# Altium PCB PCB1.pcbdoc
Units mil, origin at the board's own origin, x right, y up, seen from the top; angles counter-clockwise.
Board outline 2875 x 2510 mil, 2 copper layers (Top Layer, Bottom Layer); 42 components, 21 nets, 120 pads, 43 vias.
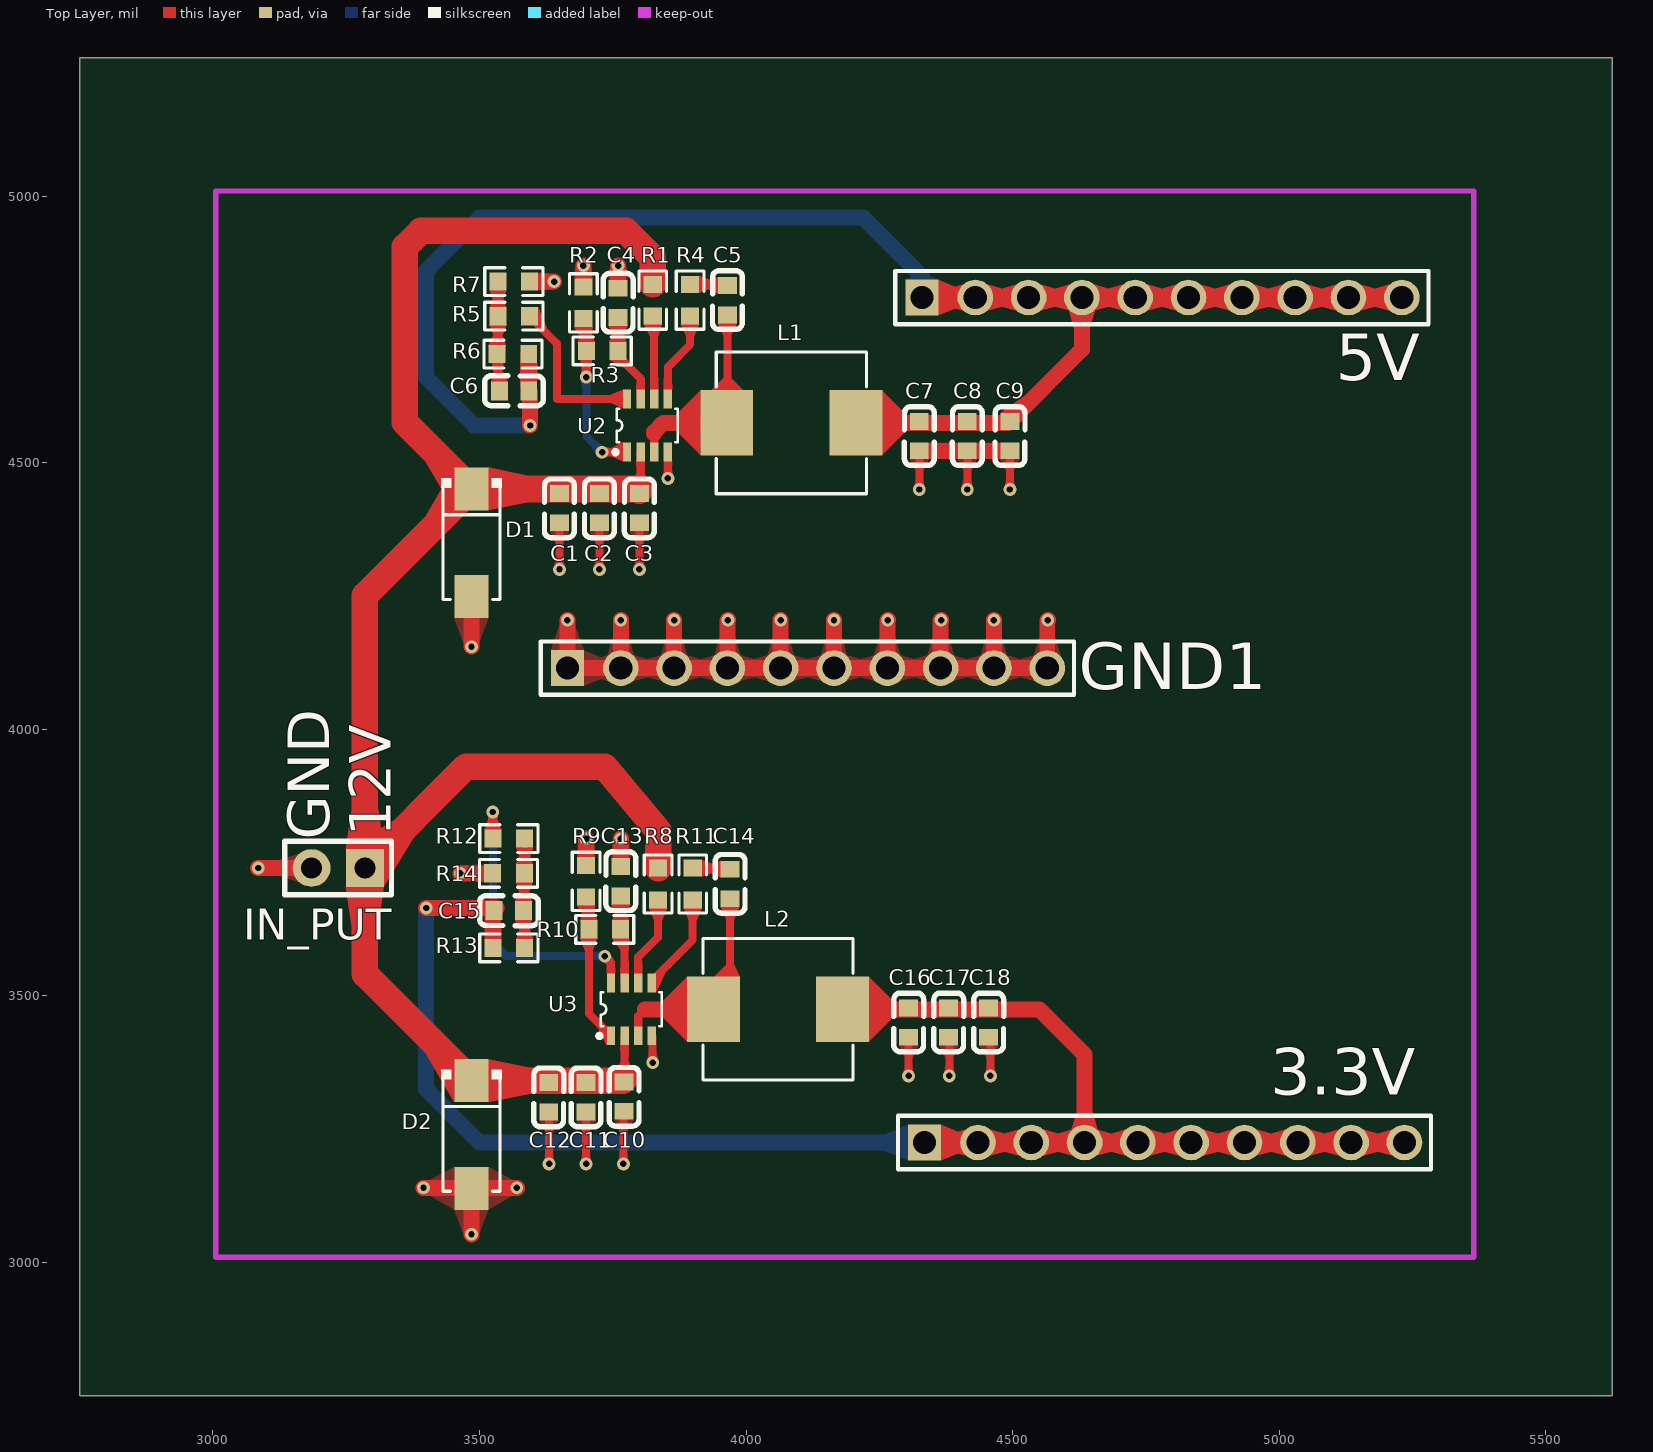
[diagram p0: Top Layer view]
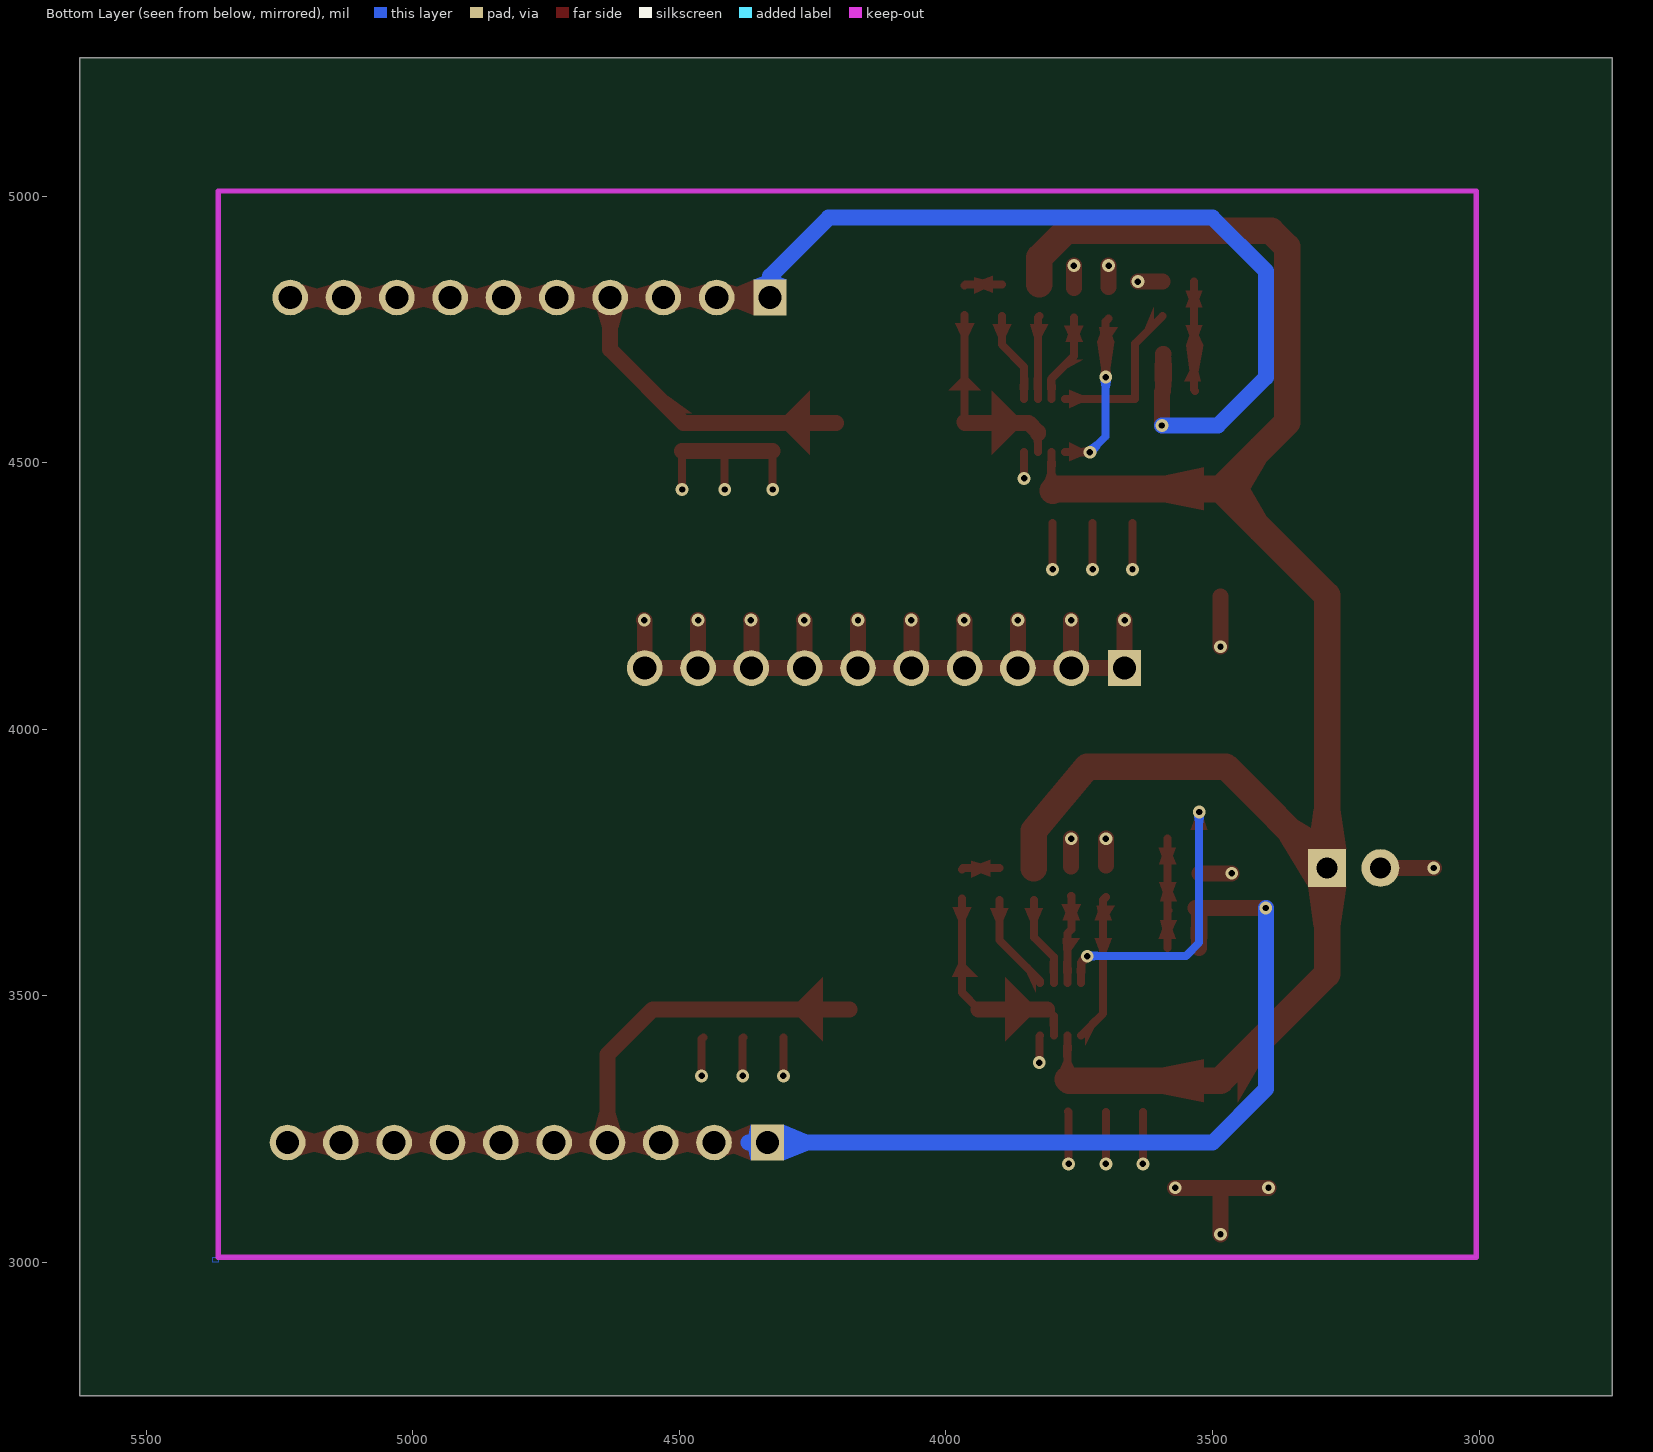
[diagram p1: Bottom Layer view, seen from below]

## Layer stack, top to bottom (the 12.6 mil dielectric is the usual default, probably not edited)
Top Layer: signal copper (thickness not stored)
Dielectric: dielectric 12.6, FR-4, Dk 4.8
Bottom Layer: signal copper (thickness not stored)

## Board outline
5625,2750 2750,2750 2750,5260 5625,5260

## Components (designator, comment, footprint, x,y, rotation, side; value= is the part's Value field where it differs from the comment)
3.3V "HDR-M_2.54_1x10P" HDR-TH_10P-P2.54-V-M-1 4785,3225 r0 top
5V "HDR-M_2.54_1x10P" HDR-TH_10P-P2.54-V-M-1 4780,4810 r0 top
C1 "CAP_0603" C0603 3650,4415 r90 top
C2 "CAP_0603" C0603 3725,4415 r90 top
C3 "CAP_0603" C0603 3800,4415 r90 top
C4 "CAP_0603" C0603 3760,4800 r270 top
C5 "CAP_0603" C0603 3965,4805 r270 top
C6 "CAP_0603" C0603 3565,4635 r0 top
C7 "CAP_0603" C0603 4325,4550 r270 top
C8 "CAP_0603" C0603 4415,4550 r270 top
C9 "CAP_0603" C0603 4495,4550 r270 top
C10 "CAP_0603" C0603 3771.35,3311.07 r90 top
C11 "CAP_0603" C0603 3700,3310 r90 top
C12 "CAP_0603" C0603 3630,3310 r90 top
C13 "CAP_0603" C0603 3765,3715 r270 top
C14 "CAP_0603" C0603 3970,3710 r270 top
C15 "CAP_0603" C0603 3555,3660 r180 top
C16 "CAP_0603" C0603 4305,3450 r270 top
C17 "CAP_0603" C0603 4380,3450 r270 top
C18 "CAP_0603" C0603 4455,3450 r270 top
D1 "SMAJ12A_C220440" SMA_L4.4-W2.8-LS5.4-RD 3485,4350 r270 top
D2 "SMAJ12A_C220440" SMA_L4.4-W2.8-LS5.4-RD 3485,3240 r270 top
GND1 "HDR-M_2.54_1x10P" HDR-TH_10P-P2.54-V-M-1 4115,4115 r0 top
IN_PUT "HDR-M_2.54_1x2P" HDR-TH_2P-P2.54-V-M-1 3235,3740 r180 top
L1 "MHCI06030-4R7M-R8" IND-SMD_L7.3-W6.6_MHCI06030 4085,4575 r0 top
L2 "MHCI06030-4R7M-R8" IND-SMD_L7.3-W6.6_MHCI06030 4060,3475 r0 top
R1 "Res_0603" R0603 3825,4805 r270 top
R2 "Res_0603" R0603 3695,4800 r270 top
R3 "Res_0603" R0603 3730,4710 r0 top
R4 "Res_0603" R0603 3895,4805 r90 top
R5 "Res_0603" R0603 3564.39,4775 r180 top
R6 "Res_0603" R0603 3562.72,4703.95 r0 top
R7 "Res_0603" R0603 3564.39,4840 r180 top
R8 "Res_0603" R0603 3835,3710 r270 top
R9 "Res_0603" R0603 3700,3715 r270 top
R10 "Res_0603" R0603 3735,3625 r0 top
R11 "Res_0603" R0603 3900,3710 r90 top
R12 "Res_0603" R0603 3555,3795 r0 top
R13 "Res_0603" R0603 3555,3590 r180 top
R14 "Res_0603" R0603 3554.39,3729.99 r0 top
U2 "MP2315SGJ-Z" TSOT-23-8_L2.9-W1.6-P0.65-LS2.8-BL 3815,4570 r0 top
U3 "MP2315SGJ-Z" TSOT-23-8_L2.9-W1.6-P0.65-LS2.8-BL 3785,3475 r0 top

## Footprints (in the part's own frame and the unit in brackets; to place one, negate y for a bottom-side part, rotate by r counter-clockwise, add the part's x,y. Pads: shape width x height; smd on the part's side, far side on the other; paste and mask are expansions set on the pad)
C0603 [mm]
  rect 0.8x0.9 smd: 1(-0.7,0) 2(0.7,0)
  silkscreen extent -1.41,-0.71 1.39,0.72
HDR-TH_2P-P2.54-V-M-1 [mm]
  rect 1.8x1.8 hole 1: 1(-1.27,0)
  round 1.8 hole 1: 2(1.27,0)
  silkscreen extent -2.54,-1.27 2.54,1.27
HDR-TH_10P-P2.54-V-M-1 [mm]
  rect 1.575x1.7 hole 1.1: 1(-11.43,0)
  round 1.7 hole 1.1: 2(-8.89,0) 3(-6.35,0) 4(-3.81,0) 5(-1.27,0) 6(1.27,0) 7(3.81,0) 8(6.35,0) 9(8.89,0) 10(11.43,0)
  silkscreen extent -12.7,-1.27 12.7,1.27
IND-SMD_L7.3-W6.6_MHCI06030 [mm]
  rect 2.524x3.12 smd: 1(-3.078,0) 2(3.078,0)
  silkscreen extent -3.58,-3.38 3.58,3.38
R0603 [mil]
  rect 31.75x34.02 smd: 1(-29.66,0) 2(29.66,0)
  silkscreen extent -55,-26 55,26
SMA_L4.4-W2.8-LS5.4-RD [mil]
  rect 80.57x63.78 smd: 1(-101,0) 2(101,0)
  silkscreen extent -121,-57 106,57
TSOT-23-8_L2.9-W1.6-P0.65-LS2.8-BL [mm]
  rect 0.4x0.9 smd: 1(-0.975,-1.26) 2(-0.325,-1.26) 3(0.325,-1.26) 4(0.975,-1.26) 5(0.975,1.26) 6(0.325,1.26) 7(-0.325,1.26) 8(-0.975,1.26)
  silkscreen extent -1.62,-1.37 1.45,0.8

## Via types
v1: diameter 24.02, hole 12.01, Top Layer to Bottom Layer, 43 vias

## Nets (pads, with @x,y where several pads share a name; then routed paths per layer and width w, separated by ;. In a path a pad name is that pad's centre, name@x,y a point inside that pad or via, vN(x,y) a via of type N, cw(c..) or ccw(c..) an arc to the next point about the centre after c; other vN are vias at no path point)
$1N440: R1.2 U2.6 | length 156.9
  Top Layer w15: R1.2 3827.8,4772.55 U2.6
$1N712: C4.2 R3.2 U2.7 | length 170.8
  Top Layer w15: R3.2@3759.66,4700 R3.2@3760,4700.34 ; C4.2 R3.2@3760,4700.34 ; U2.7 3802.2,4658.14 R3.2@3760,4700.34
$1N792: R2.2 R3.1 U2.1 | length 311.6
  Top Layer w15: R2.2 3700.34,4765 v1(3700.34,4660.87) ; v1(3730,4520) 3776.22,4520 U2.1
  Bottom Layer w15: v1(3700.34,4660.87) 3700.34,4549.66 v1(3730,4520)
$1N1001: R4.1 U2.5 | length 173
  Top Layer w15: U2.5 3853.39,4680 3895,4721.61 R4.1
$1N1049: C5.1 R4.2 | length 70.9
  Top Layer w15: R4.2 3962.9,4834.66 C5.1
$1N1375: C5.2 L1.1 U2.3 | length 383.5
  Top Layer w15: U2.3 3827.8,4555 ; L1.1@3965,4576.18 C5.2
  Top Layer w30: 3827.8,4555 3827.8,4557.8 3845,4575 L1.1 L1.1@3965,4576.18
$1N1427: R5.1 U2.8 | length 307.9
  Top Layer w15: R5.1 3645,4724.05 3645,4620 3776.22,4620 U2.8
$1N1780: C6.1 R5.2 R6.1 R7.2 | length 205.9
  Top Layer w15: C6.1@3532.44,4635 3534.73,4637.29 R5.2 R7.2
$1N2972: R8.2 U3.6 | length 171.1
  Top Layer w15: U3.6 3797.8,3572.8 3835,3610 R8.2
$1N2996: C13.2 R10.2 U3.7 | length 166.1
  Top Layer w15: C13.2 3764.66,3687.1 R10.2 3772.2,3617.45 U3.7
$1N3001: R9.2 R10.1 U3.1 | length 279.3
  Top Layer w15: R9.2 3705.34,3680 R10.1 3705.34,3466.67 U3.1
$1N3008: R11.1 U3.5 | length 187.5
  Top Layer w15: U3.5 3823.39,3528.39 3900,3605 R11.1
$1N3010: C14.1 R11.2 | length 70.9
  Top Layer w15: R11.2 3967.9,3739.66 C14.1
$1N3012: C14.2 L2.1 U3.3 | length 403.8
  Top Layer w15: U3.3 3797.8,3462.8 3810,3475 ; L2.1 3970,3506.18 C14.2
  Top Layer w30: 3810,3475 L2.1
$1N3019: R12.1 U3.8 | length 570.4
  Top Layer w15: v1(3525,3845) 3525.34,3844.66 R12.1 ; v1(3735,3574.5) 3746.61,3562.88 U3.8
  Bottom Layer w15: v1(3525,3845) 3525,3600 3550,3575 3734.5,3575 v1(3735,3574.5)
$1N3044: C15.1 R12.2 R13.1 R14.2 | length 206.7
  Top Layer w15: R13.1 3584.66,3657.9 C15.1 3584.05,3661.49 R14.2 3584.66,3730.6 R12.2
+3.3V: 3.3V.1 3.3V.2 3.3V.3 3.3V.4 3.3V.5 3.3V.6 3.3V.7 3.3V.8 3.3V.9 3.3V.10 C15.2 C16.1 C17.1 C18.1 L2.2 R13.2 | length 3115
  Top Layer w30: v1(3400,3665) 3531.82,3665 3525.34,3658.52 R13.2 ; L2.2 4550,3475 4635,3390 3.3V.4 ; 3.3V.1 3.3V.2 3.3V.3 3.3V.4 ; 3.3V.10 3.3V.9 3.3V.8 3.3V.7 3.3V.6 3.3V.5 3.3V.4
  Bottom Layer w30: v1(3400,3665) 3400,3325 3500,3225 3.3V.1 4370,3225
+5V: 5V.1 5V.2 5V.3 5V.4 5V.5 5V.6 5V.7 5V.8 5V.9 5V.10 C6.2 C7.1 C8.1 C9.1 L1.2 R6.2 | length 3097.9
  Top Layer w30: R6.2 3592.56,4703.76 C6.2@3592.56,4639.63 ; C6.2 3595,4632.56 v1(3595,4570) ; L1.2 4492.44,4575 4630,4712.56 5V.4 ; 5V.1 5V.2 5V.3 5V.4 ; 5V.10 5V.9 5V.8 5V.7 5V.6 5V.5 5V.4
  Bottom Layer w30: v1(3595,4570) 3490,4570 3400,4660 3400,4860 3500,4960 4220,4960 4330,4850 5V.1
+12V: C1.2 C2.2 C3.2 C10.2 C11.2 C12.2 D1.1 D2.1 IN_PUT.1 R1.1 R8.1 U2.2 U3.2 | length 3843.7
  Top Layer w15: C10.2@3772.2,3344.48 U3.2 ; C3.2@3800,4447.56 3802.2,4449.77 U2.2
  Top Layer w50: C10.2@3771.35,3343.63 3768.72,3341 D2.1 3285,3541 IN_PUT.1 ; C3.2@3800,4447.56 3796.56,4451 D1.1 ; R1.1 3825,4885 3775,4935 3390,4935 3360,4905 3360,4576 D1.1 ; R8.1 3835,3810 3735,3930 3475,3930 IN_PUT.1 ; IN_PUT.1 3285,4251 D1.1
GND: C1.1 C2.1 C3.1 C4.1 C7.2 C8.2 C9.2 C10.1 C11.1 C12.1 C13.1 C16.2 C17.2 C18.2 D1.2 D2.2 GND1.1 GND1.2 GND1.3 GND1.4 GND1.5 GND1.6 GND1.7 GND1.8 GND1.9 GND1.10 IN_PUT.2 R2.1 R7.1 R9.1 R14.1 U2.4 U3.4 | length 3813.5
  Top Layer w15: C12.1 3630.49,3281.95 v1(3630.49,3185) ; v1(3650,4300) C1.1 ; v1(3700.01,3185) C11.1 ; v1(3725,4300) C2.1 ; v1(3770,3185) 3770,3282.16 C10.1 ; v1(3800,4300) C3.1 ; U3.4 3825,3423.78 v1(3825,3375) ; v1(3853.39,4470.71) U2.4 ; v1(4305,3350) C16.2 ; v1(4325,4450) C7.2 ; C17.2 4381.2,3421.24 v1(4381.2,3350) ; v1(4415,4450) C8.2 ; C18.2 4458.35,3419.09 v1(4458.35,3350) ; v1(4495,4450) C9.2
  Top Layer w30: v1(3085,3740) IN_PUT.2 ; v1(3395,3140) 3484,3140 D2.2 ; v1(3464.09,3729.99) R14.1 ; v1(3485,3052.8) D2.2 ; v1(3485,4155) D1.2 ; v1(3570,3140) 3486,3140 D2.2 ; R7.1 v1(3640,4840) ; v1(3665,4205) GND1.1 GND1.2 ; R2.1 v1(3695,4870) ; R9.1 v1(3700,3795) ; C4.1 v1(3760,4870) ; C13.1 v1(3765,3795) ; v1(3765,4205) GND1.2 ; v1(3865,4205) GND1.3 ; v1(3965.97,4205) 3965,4204.03 GND1.4 ; v1(4065,4205) GND1.5 ; v1(4165,4205) GND1.6 ; v1(4265.97,4205) 4265,4204.03 GND1.7 ; C7.2 C8.2 C9.2 ; v1(4365.97,4205) 4365,4204.03 GND1.8 ; v1(4465,4205) GND1.9 ; v1(4565.97,4205) 4565,4204.03 GND1.10 GND1.9 ; GND1.2 GND1.3 ; GND1.3 GND1.4 ; GND1.4 GND1.5 ; GND1.5 GND1.6 ; GND1.6 GND1.7 ; GND1.7 GND1.8 ; GND1.8 GND1.9
  other v1: 3853.39,4470.71 3853.39,4470.71
"": 

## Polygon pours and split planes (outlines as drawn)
GND on Bottom Layer (solid, remove dead copper, pour order 1): 5365,3000 5375,3000 5375,3010 5365,3010
GND on Bottom Layer (solid, pour order 2): 3005,3010 5365,3010 5365,5010 3005,5010
GND on Top Layer (solid, remove dead copper, pour order 0): 3000,3010 5365,3010 5365,5010 3000,5010

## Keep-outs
Board Outline Layer:
  lines w10 net "": 3005,3010 5365,3010 5365,5010 3005,5010 3005,3010

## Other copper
Top Layer:
  region net +12V: 3809.7,4480.81 3794.7,4480.81 3782.28,4458.31 3817.72,4458.31
  region net $1N712: 3752.5,4734.19 3767.5,4734.19 3777.72,4756.69 3742.28,4756.69
  region net $1N792: 3692.84,4731.96 3707.84,4731.96 3712.01,4754.46 3677.99,4754.46
  region net $1N712: 3772.65,4677.08 3791.45,4679.5 3775.54,4692.99 3743.78,4692.99
  region net $1N712: 3752.5,4749.51 3743.78,4727.01 3775.54,4727.01 3767.5,4749.51
  region net $1N792: 3692.84,4670.49 3707.84,4670.49 3716.22,4727.01 3684.46,4727.01
  region net $1N792: 3692.84,4749.51 3684.46,4727.01 3716.22,4727.01 3707.84,4749.51
  region net +12V: 3400.08,4401.43 3427.04,4357.68 3453.11,4410.72 3453.11,4491.28
  region net +12V: 3591.89,4476 3516.89,4491.28 3516.89,4410.72 3591.89,4426
  region net +12V: 3400.08,4500.57 3453.11,4410.72 3453.11,4491.28 3427.04,4544.32
  region net $1N1049: 3934.51,4842.16 3912.01,4850.54 3912.01,4818.78 3934.51,4827.16
  region net $1N1001: 3887.5,4736.96 3902.5,4736.96 3912.01,4759.46 3877.99,4759.46
  region net $1N1375: 3972.5,4739.19 3982.72,4761.69 3947.28,4761.69 3957.5,4739.19
  region net $1N1049: 3924.78,4842.16 3924.78,4827.16 3947.28,4816.81 3947.28,4848.31
  region net +5V: 4300.86,4590 4255.86,4635 4255.86,4515 4300.86,4560
  region net $1N1375: 3972.5,4658.92 3957.5,4658.92 3935,4636.42 3995,4636.42
  region net $1N1375: 3869.14,4560 3914.14,4515 3914.14,4635 3869.14,4590
  region net $1N1780: 3542.23,4814.51 3527.23,4814.51 3518.85,4792.01 3550.61,4792.01
  region net $1N1780: 3542.23,4735.49 3550.61,4757.99 3518.85,4757.99 3527.23,4735.49
  region net $1N1427: 3616.36,4742.08 3625.84,4753.82 3609.93,4792.01 3609.93,4757.99
  region net +5V: 3577.56,4641.94 3607.56,4641.94 3608.25,4686.94 3576.5,4686.94
  region net $1N1780: 3542.23,4743.45 3527.23,4743.45 3517.18,4720.95 3548.93,4720.95
  region net $1N1780: 3542.23,4664.44 3548.93,4720.95 3517.18,4720.95 3527.23,4664.44
  region net +5V: 3577.56,4697.72 3576.81,4652.72 3608.31,4652.72 3607.56,4697.72
  region net $1N1780: 3542.23,4675.22 3527.23,4675.22 3521.69,4652.72 3553.19,4652.72
  region net $1N1780: 3542.23,4800.49 3550.61,4822.99 3518.85,4822.99 3527.23,4800.49
  region net +5V: 4544.54,4605.88 4521.35,4625.13 4477.28,4593.31 4512.72,4593.31
  region net $1N440: 3820.3,4736.96 3835.3,4736.96 3842.01,4759.46 3807.99,4759.46
  region net $1N792: 3746.24,4512.5 3768.74,4502.68 3768.74,4538.11 3746.24,4527.5
  region net +12V: 3809.7,4480.18 3810.08,4502.68 3794.33,4502.68 3794.7,4480.18
  region net $1N1375: 3820.3,4555 3819.92,4538.11 3835.67,4538.11 3835.3,4555
  region net $1N1001: 3845.89,4659.82 3845.51,4637.32 3861.26,4637.32 3860.89,4659.82
  region net $1N440: 3820.3,4659.82 3819.92,4637.32 3835.67,4637.32 3835.3,4659.82
  region net $1N712: 3794.7,4658.14 3794.33,4637.32 3810.08,4637.32 3809.7,4658.14
  region net $1N1427: 3746.24,4612.5 3768.74,4601.89 3768.74,4637.32 3746.24,4627.5
  region net +5V: 5207.87,4835.1 5173.11,4825 5173.11,4795 5207.87,4784.9
  region net +5V: 5107.87,4835.1 5073.11,4825 5073.11,4795 5107.87,4784.9
  region net +5V: 5152.13,4784.9 5186.89,4795 5186.89,4825 5152.13,4835.1
  region net +5V: 5007.87,4835.1 4973.11,4825 4973.11,4795 5007.87,4784.9
  region net +5V: 5052.13,4784.9 5086.89,4795 5086.89,4825 5052.13,4835.1
  region net +5V: 4907.87,4835.1 4873.11,4825 4873.11,4795 4907.87,4784.9
  region net +5V: 4952.13,4784.9 4986.89,4795 4986.89,4825 4952.13,4835.1
  region net +5V: 4807.87,4835.1 4773.11,4825 4773.11,4795 4807.87,4784.9
  region net +5V: 4852.13,4784.9 4886.89,4795 4886.89,4825 4852.13,4835.1
  region net +5V: 4707.87,4835.1 4673.11,4825 4673.11,4795 4707.87,4784.9
  region net +5V: 4752.13,4784.9 4786.89,4795 4786.89,4825 4752.13,4835.1
  region net +5V: 4607.87,4835.1 4573.11,4825 4573.11,4795 4607.87,4784.9
  region net +5V: 4604.9,4787.87 4615,4753.11 4645,4753.11 4655.1,4787.87
  region net +5V: 4652.13,4784.9 4686.89,4795 4686.89,4825 4652.13,4835.1
  region net +5V: 4507.87,4835.1 4473.11,4825 4473.11,4795 4507.87,4784.9
  region net +5V: 4552.13,4784.9 4586.89,4795 4586.89,4825 4552.13,4835.1
  region net +5V: 4407.87,4835.1 4373.11,4825 4373.11,4795 4407.87,4784.9
  region net +5V: 4452.13,4784.9 4486.89,4795 4486.89,4825 4452.13,4835.1
  region net +5V: 4406,4795 4406,4825 4361,4843.46 4361,4776.54
  region net +12V: 3338.11,3828.47 3249.57,3775.43 3320.43,3704.57 3373.47,3793.11
  region net +12V: 3260,3850.43 3249.57,3775.43 3320.43,3775.43 3310,3850.43
  region net +12V: 3260,3629.57 3310,3629.57 3320.43,3704.57 3249.57,3704.57
  region net $1N2972: 3827.5,3641.96 3842.5,3641.96 3852.01,3664.46 3817.99,3664.46
  region net $1N3001: 3722.83,3438.57 3738.74,3407.68 3738.74,3443.11 3723.6,3459.02
  region net +12V: 3779.7,3385.18 3780.08,3407.68 3764.33,3407.68 3764.7,3385.18
  region net $1N3012: 3790.3,3462.8 3789.92,3443.11 3805.67,3443.11 3805.3,3462.8
  region net $1N3008: 3842.62,3558.23 3831.26,3542.32 3831.26,3506.89 3847.17,3541.56
  region net $1N2972: 3790.3,3564.82 3789.92,3542.32 3805.67,3542.32 3805.3,3564.82
  region net $1N2996: 3764.7,3564.82 3764.33,3542.32 3780.08,3542.32 3779.7,3564.82
  region net $1N3019: 3739.11,3562.88 3738.74,3542.32 3754.49,3542.32 3754.11,3562.88
  region net +12V: 3779.7,3376.88 3764.7,3376.88 3753.63,3354.38 3789.07,3354.38
  region net $1N2996: 3757.16,3649.19 3772.16,3649.19 3782.72,3671.69 3747.28,3671.69
  region net $1N3001: 3697.84,3646.96 3712.84,3646.96 3717.01,3669.46 3682.99,3669.46
  region net $1N2996: 3764.7,3585.49 3779.7,3585.49 3780.54,3607.99 3748.78,3607.99
  region net $1N2996: 3757.16,3664.51 3748.78,3642.01 3780.54,3642.01 3772.16,3664.51
  region net $1N3001: 3697.84,3664.51 3689.46,3642.01 3721.22,3642.01 3712.84,3664.51
  region net $1N3001: 3697.84,3585.49 3712.84,3585.49 3721.22,3607.99 3689.46,3607.99
  region net +12V: 3591.89,3366 3516.89,3381.28 3516.89,3300.72 3591.89,3316
  region net +12V: 3400.08,3390.57 3453.11,3300.72 3453.11,3381.28 3427.04,3434.32
  region net $1N3010: 3939.51,3747.16 3917.01,3755.54 3917.01,3723.78 3939.51,3732.16
  region net $1N3008: 3892.5,3641.96 3907.5,3641.96 3917.01,3664.46 3882.99,3664.46
  region net $1N3012: 3977.5,3644.19 3987.72,3666.69 3952.28,3666.69 3962.5,3644.19
  region net $1N3010: 3929.78,3747.16 3929.78,3732.16 3952.28,3721.81 3952.28,3753.31
  region net +3.3V: 4275.86,3460 4275.86,3490 4230.86,3535 4230.86,3415
  region net $1N3012: 3844.14,3460 3889.14,3415 3889.14,3535 3844.14,3490
  region net $1N3012: 3977.5,3558.92 3962.5,3558.92 3940,3536.42 3988.51,3536.42
  region net $1N3044: 3592.16,3755.49 3600.54,3777.99 3568.78,3777.99 3577.16,3755.49
  region net $1N3019: 3532.84,3834.51 3517.84,3834.51 3509.46,3812.01 3541.22,3812.01
  region net +3.3V: 3510.34,3652.01 3509.46,3607.01 3541.22,3607.01 3540.34,3652.01
  region net $1N3044: 3592.16,3629.51 3577.16,3629.51 3568.78,3607.01 3600.54,3607.01
  region net $1N3044: 3591.55,3700.22 3576.55,3700.22 3566.81,3677.72 3598.31,3677.72
  region net $1N3044: 3592.16,3619.78 3598.31,3642.28 3566.81,3642.28 3577.16,3619.78
  region net $1N3044: 3592.16,3769.5 3577.16,3769.5 3568.17,3747 3599.93,3747
  region net $1N3044: 3591.55,3690.49 3599.93,3712.99 3568.17,3712.99 3576.55,3690.49
  region net +3.3V: 5212.87,3250.1 5178.11,3240 5178.11,3210 5212.87,3199.9
  region net +3.3V: 5112.87,3250.1 5078.11,3240 5078.11,3210 5112.87,3199.9
  region net +3.3V: 5157.13,3199.9 5191.89,3210 5191.89,3240 5157.13,3250.1
  region net +3.3V: 5012.87,3250.1 4978.11,3240 4978.11,3210 5012.87,3199.9
  region net +3.3V: 5057.13,3199.9 5091.89,3210 5091.89,3240 5057.13,3250.1
  region net +3.3V: 4912.87,3250.1 4878.11,3240 4878.11,3210 4912.87,3199.9
  region net +3.3V: 4957.13,3199.9 4991.89,3210 4991.89,3240 4957.13,3250.1
  region net +3.3V: 4812.87,3250.1 4778.11,3240 4778.11,3210 4812.87,3199.9
  region net +3.3V: 4857.13,3199.9 4891.89,3210 4891.89,3240 4857.13,3250.1
  region net +3.3V: 4712.87,3250.1 4678.11,3240 4678.11,3210 4712.87,3199.9
  region net +3.3V: 4757.13,3199.9 4791.89,3210 4791.89,3240 4757.13,3250.1
  region net +3.3V: 4612.87,3250.1 4578.11,3240 4578.11,3210 4612.87,3199.9
  region net +3.3V: 4660.1,3247.13 4650,3281.89 4620,3281.89 4609.9,3247.13
  region net +3.3V: 4657.13,3199.9 4691.89,3210 4691.89,3240 4657.13,3250.1
  region net +3.3V: 4512.87,3250.1 4478.11,3240 4478.11,3210 4512.87,3199.9
  region net +3.3V: 4557.13,3199.9 4591.89,3210 4591.89,3240 4557.13,3250.1
  region net +3.3V: 4412.87,3250.1 4378.11,3240 4378.11,3210 4412.87,3199.9
  region net +3.3V: 4457.13,3199.9 4491.89,3210 4491.89,3240 4457.13,3250.1
  region net +3.3V: 4411,3210 4411,3240 4366,3258.46 4366,3191.54
  region net $1N792: 3737.94,4510.99 3750.41,4512.5 3750.41,4527.5 3737.94,4529.01
  region net $1N3019: 3734.25,3562.52 3741.31,3557.58 3751.92,3568.19 3746.98,3575.25
  region net $1N3019: 3516.22,3836.81 3517.84,3824.38 3532.84,3824.8 3534.23,3837.32
  region net $1N792: 3709.35,4668.82 3707.84,4681.29 3692.84,4681.29 3691.33,4668.82
Bottom Layer:
  region net +5V: 4345,4850 4315,4850 4299,4843.46 4361,4843.46
  region net +3.3V: 4259,3240 4259,3210 4304,3191.54 4304,3258.46
  region net +3.3V: 4370,3240 4366,3258.46 4366,3191.54 4370,3210
  region net $1N792: 3730.75,4531.98 3720.87,4539.74 3710.26,4529.13 3718.02,4519.25
  region net $1N3019: 3727.44,3583.83 3714.9,3582.5 3714.28,3567.5 3726.69,3565.83
  region net $1N3019: 3515.99,3837.06 3517.5,3824.59 3532.5,3824.59 3534.01,3837.06
  region net $1N792: 3691.33,4652.93 3692.84,4640.46 3707.84,4640.46 3709.35,4652.93

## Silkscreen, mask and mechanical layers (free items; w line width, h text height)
Top Silkscreen Layer:
  text "12V" at 3333.36,3798.35 h77.88 r90
  text "GND" at 3218.36,3793.35 h77.88 r90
